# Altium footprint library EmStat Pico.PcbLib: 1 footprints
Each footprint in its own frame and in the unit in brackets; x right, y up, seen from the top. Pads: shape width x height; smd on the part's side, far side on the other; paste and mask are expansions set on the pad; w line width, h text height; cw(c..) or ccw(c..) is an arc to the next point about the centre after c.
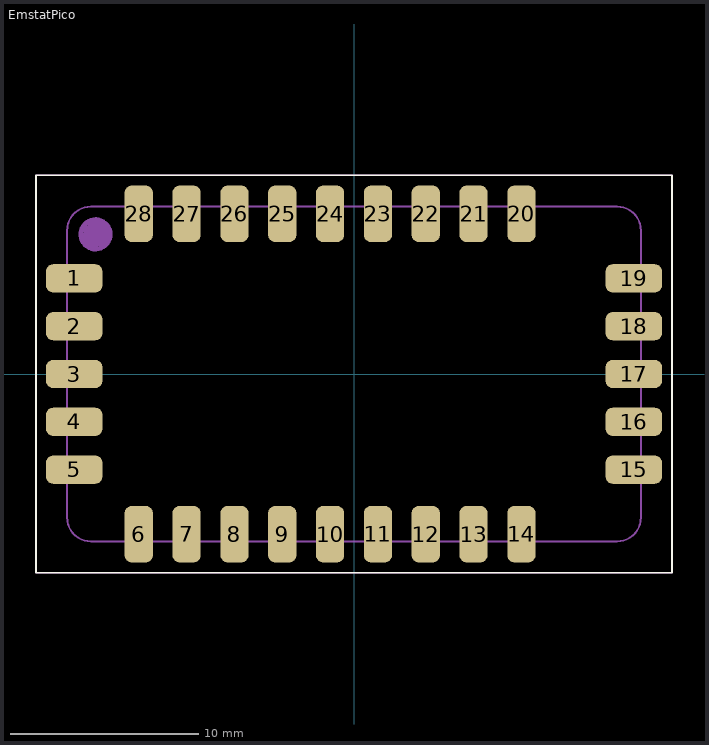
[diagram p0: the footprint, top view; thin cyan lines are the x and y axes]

## EmstatPico [mm] "EmStat Pico LandPattern"
pads (28):
  rrect50% 3x1.5 smd: 1(-14.859,5.08) 2(-14.859,2.54) 3(-14.859,0) 4(-14.859,-2.54) 5(-14.859,-5.08) 15(14.859,-5.08) 16(14.859,-2.54) 17(14.859,0) 18(14.859,2.54) 19(14.859,5.08)
  rrect50% 1.5x3 smd: 6(-11.43,-8.509) 7(-8.89,-8.509) 8(-6.35,-8.509) 9(-3.81,-8.509) 10(-1.27,-8.509) 11(1.27,-8.509) 12(3.81,-8.509) 13(6.35,-8.509) 14(8.89,-8.509) 20(8.89,8.509) 21(6.35,8.509) 22(3.81,8.509) 23(1.27,8.509) 24(-1.27,8.509) 25(-3.81,8.509) 26(-6.35,8.509) 27(-8.89,8.509) 28(-11.43,8.509)
Top Overlay:
  lines w0.1: -16.9,-10.559 -16.9,10.559 16.9,10.559 16.9,-10.559 -16.9,-10.559
Mechanical 6:
  lines w0.1: -16.9,-10.559 16.9,-10.559 16.9,10.559 -16.9,10.559 -16.9,-10.559
Mechanical 8:
  circle w0.254: c-13.73,7.42 r0.781
  circle w0.254: c-13.73,7.42 r0.539
  circle w0.254: c-13.73,7.42 r0.1
  circle w0.254: c-13.73,7.42 r0.316
  lines w0.1: -15.24,-7.62 ccw(c-13.97,-7.62) -13.97,-8.89 13.97,-8.89 ccw(c13.97,-7.62) 15.24,-7.62 15.24,7.62 ccw(c13.97,7.62) 13.97,8.89 -13.97,8.89 ccw(c-13.97,7.62) -15.24,7.62 -15.24,-7.62
Mechanical 11:
  circle w0.254: c-13.73,7.42 r0.1
  circle w0.254: c-13.73,7.42 r0.316
  circle w0.254: c-13.73,7.42 r0.539
  circle w0.254: c-13.73,7.42 r0.781
  lines w0.1: -15.24,-7.62 ccw(c-13.97,-7.62) -13.97,-8.89 13.97,-8.89 ccw(c13.97,-7.62) 15.24,-7.62 15.24,7.62 ccw(c13.97,7.62) 13.97,8.89 -13.97,8.89 ccw(c-13.97,7.62) -15.24,7.62 -15.24,-7.62
3D body "ES_pico_V1-1_with_Can.step": height 2.6, standoff 0, extent -15.3,-8.89 15.18,8.89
